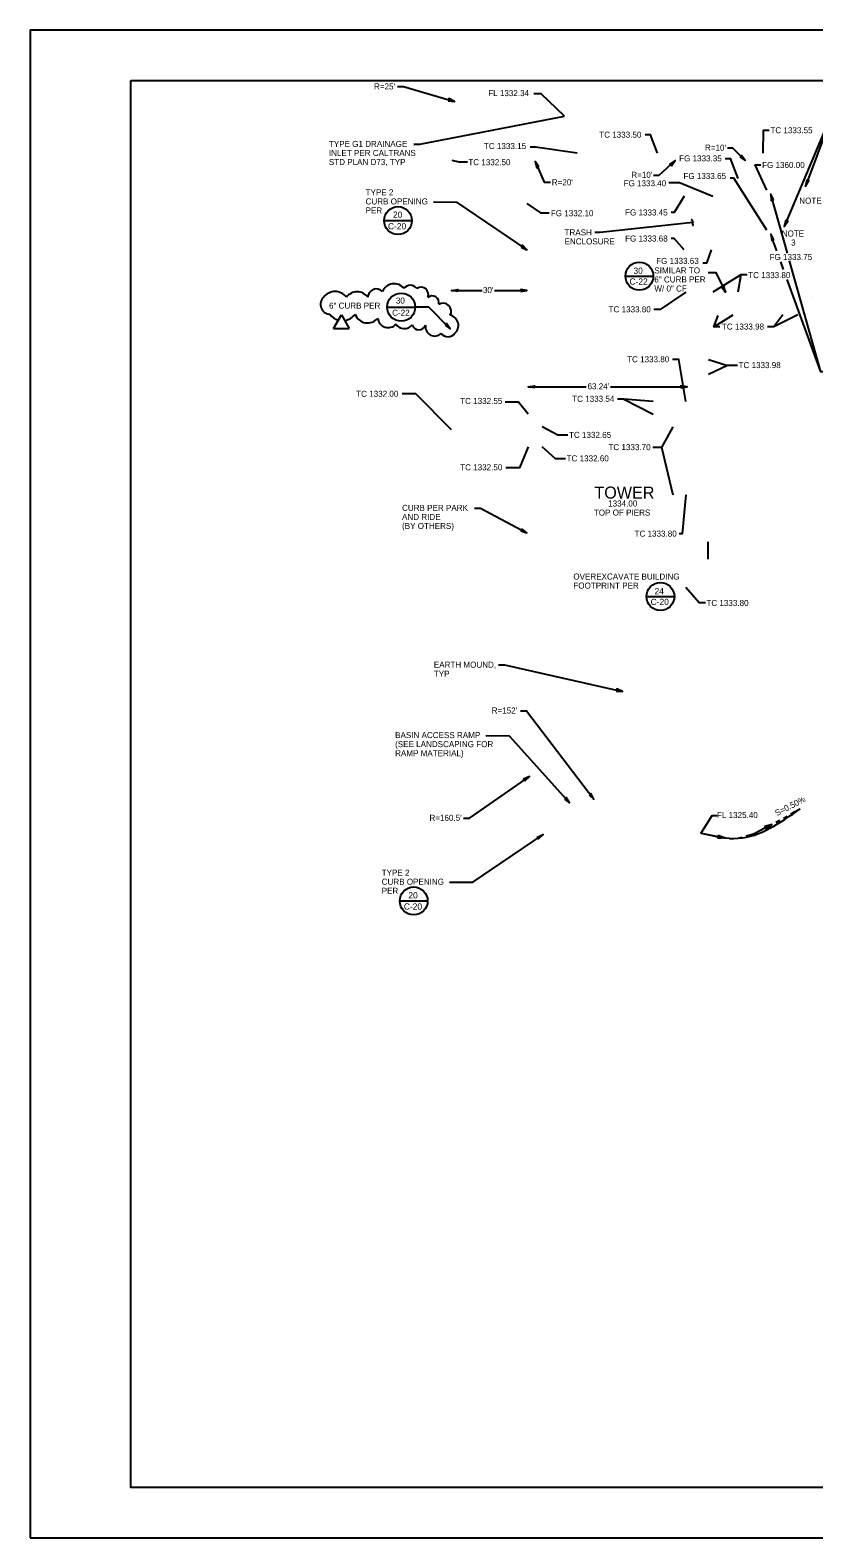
# Model space of a CAD drawing. Extents: x 0 to 3.5, y 0 to 3.39.
# Drawn here: x 0 to 1.299, y 0 to 2.5 of the extents above; entities that cross this region are included whole.
import ezdxf

# ---------------------------------------------------------------- set-up
doc = ezdxf.new("R2010")
doc.units = 0
for name, color, linetype in [('A-FLOR-PATT', 7, 'Continuous'), ('C-FLOW-Swale', 7, 'Continuous'), ('C-MARK', 7, 'Continuous'), ('C-MATC', 7, 'Continuous'), ('C-REVC', 7, 'Continuous'), ('C-TEXT', 7, 'Continuous'), ('C-TEXT-TITL', 7, 'Continuous'), ('G-TTLB-OTLN', 7, 'Continuous'), ('G-TTLB-VIEW', 7, 'Continuous')]:
    doc.layers.add(name, color=color, linetype=linetype)

msp = doc.modelspace()

# ---------------------------------------------------------------- linework, layer by layer
at = {"layer": 'A-FLOR-PATT'}
msp.add_line((1.2971, 2.0571), (1.2969, 2.0571), dxfattribs=at)
at = {"layer": 'C-FLOW-Swale'}
for p, q in [((1.2179, 1.1799), (1.2301, 1.1833)), ((1.2192, 1.1776), (1.2179, 1.1799)), ((1.2192, 1.1776), (1.2204, 1.1752)), ((1.2301, 1.1833), (1.2204, 1.1752)), ((1.14, 1.1628), (1.1395, 1.1602)), ((1.1522, 1.1608), (1.1396, 1.16)), ((1.14, 1.1628), (1.1406, 1.1654)), ((1.1404, 1.1653), (1.1522, 1.1608))]:
    msp.add_line(p, q, dxfattribs=at)
for points in [[(1.2611, 1.2002), (1.2672, 1.2036)], [(1.2672, 1.2036), (1.2765, 1.2088)], [(1.1936, 1.1658), (1.2003, 1.1677), (1.2192, 1.1776)], [(1.2182, 1.1793), (1.221, 1.1807)], [(1.2185, 1.1787), (1.224, 1.1816)], [(1.2189, 1.1781), (1.2271, 1.1824)], [(1.2192, 1.1776), (1.2301, 1.1833)], [(1.2195, 1.177), (1.2277, 1.1813)], [(1.2198, 1.1764), (1.2252, 1.1792)], [(1.2201, 1.1758), (1.2228, 1.1772)], [(1.2364, 1.1865), (1.2385, 1.1877), (1.2426, 1.1899)], [(1.2487, 1.1933), (1.2549, 1.1968)], [(1.1124, 1.1686), (1.14, 1.1628)], [(1.1396, 1.1609), (1.1426, 1.1603)], [(1.1398, 1.1615), (1.1433, 1.1608), (1.1459, 1.1604)], [(1.1399, 1.1622), (1.1434, 1.1615), (1.149, 1.1606)], [(1.14, 1.1628), (1.1435, 1.1621), (1.1522, 1.1608)], [(1.1402, 1.1635), (1.1436, 1.1628), (1.1493, 1.1619)], [(1.1403, 1.1641), (1.1438, 1.1634), (1.1463, 1.163)], [(1.1404, 1.1648), (1.1435, 1.1642)], [(1.1592, 1.1597), (1.1662, 1.1599)], [(1.1733, 1.16), (1.174, 1.16), (1.1801, 1.1618)], [(1.1869, 1.1638), (1.1936, 1.1658)]]:
    msp.add_lwpolyline(points, dxfattribs=at)
msp.add_spline([(1.1124, 1.1686), (1.174, 1.16), (1.2765, 1.2088)], degree=3, dxfattribs=at)
at = {"layer": 'C-MARK'}
for p, q in [((1.3416, 2.3923), (1.2855, 2.2414)), ((1.1784, 2.0941), (1.1315, 2.0653)), ((0.6986, 2.0682), (0.7494, 2.0682)), ((0.7697, 2.0682), (0.8236, 2.0682)), ((1.2475, 2.0277), (1.2331, 2.0083)), ((1.1245, 1.954), (1.1559, 1.9441)), ((0.8257, 1.9086), (0.9219, 1.9086)), ((0.9622, 1.9086), (1.0892, 1.9086)), ((0.9841, 1.8882), (1.0328, 1.8632)), ((1.0474, 1.8081), (1.0661, 1.8424)), ((1.1232, 1.6514), (1.1232, 1.6227))]:
    msp.add_line(p, q, dxfattribs=at)
for points in [[(0.6089, 2.4068), (0.6189, 2.4068), (0.7035, 2.3817)], [(0.8858, 2.3575), (0.8474, 2.3944), (0.835, 2.3944)], [(1.3541, 2.3924), (1.3416, 2.3923), (1.2499, 2.1747)], [(0.6359, 2.3111), (0.6459, 2.3111), (0.8858, 2.3575)], [(1.0399, 2.2958), (1.0282, 2.3265), (1.0194, 2.3265)], [(1.2149, 2.2958), (1.2155, 2.3341), (1.2249, 2.3341)], [(0.9069, 2.2958), (0.8377, 2.306), (0.8289, 2.306)], [(1.1854, 2.2836), (1.1647, 2.3042), (1.1559, 2.3042)], [(0.6992, 2.2843), (0.7109, 2.2819), (0.725, 2.2819)], [(0.8373, 2.2822), (0.8523, 2.2477), (0.8628, 2.2477)], [(1.0694, 2.2836), (1.0424, 2.2589), (1.0336, 2.2589)], [(1.1522, 2.2871), (1.1607, 2.2871), (1.1732, 2.2542)], [(1.2211, 2.2348), (1.2018, 2.2765), (1.2112, 2.2765)], [(1.2211, 2.1681), (1.1668, 2.2547), (1.1606, 2.2547)], [(1.0588, 2.2476), (1.0763, 2.2475), (1.1315, 2.2249)], [(1.2554, 2.13), (1.2277, 2.2282)], [(0.6686, 2.2151), (0.7069, 2.2149), (0.8236, 2.136)], [(0.8236, 2.2125), (0.8463, 2.1971), (0.8604, 2.1971)], [(1.0843, 2.2249), (1.0674, 2.1979), (1.0624, 2.1979)], [(1.0985, 2.1812), (0.9448, 2.1647), (0.936, 2.1647)], [(1.0843, 2.136), (1.0675, 2.1547), (1.0625, 2.1547)], [(1.2376, 2.1341), (1.2312, 2.1517)], [(1.1288, 2.136), (1.1215, 2.1139), (1.1153, 2.1139)], [(1.249, 2.1029), (1.2443, 2.1157)], [(1.3209, 1.9332), (1.3109, 1.9332), (1.2589, 2.1176)], [(1.124, 2.0981), (1.1366, 2.0981), (1.1528, 2.0653)], [(1.1884, 2.0941), (1.1784, 2.0941), (1.1732, 2.0653)], [(1.3209, 1.9332), (1.3109, 1.9332), (1.255, 2.0863)], [(1.0869, 2.0653), (1.0446, 2.0367), (1.034, 2.0367)], [(0.6965, 2.005), (0.6608, 2.0407), (0.6382, 2.0407)], [(1.1436, 2.0083), (1.1336, 2.0083), (1.1657, 2.0278)], [(1.1436, 2.0083), (1.1336, 2.0083), (1.1407, 2.0268)], [(1.2725, 2.0277), (1.2331, 2.0083), (1.2226, 2.0083)], [(1.0869, 1.884), (1.0751, 1.9538), (1.0646, 1.9538)], [(1.1727, 1.9441), (1.1559, 1.9441), (1.1245, 1.929)], [(0.6986, 1.8371), (0.6393, 1.897), (0.6167, 1.897)], [(0.8257, 1.8632), (0.8097, 1.8831), (0.7872, 1.8831)], [(1.0328, 1.884), (0.9841, 1.8882), (0.9736, 1.8882)], [(0.8916, 1.8284), (0.8748, 1.8284), (0.8486, 1.8424)], [(0.8257, 1.809), (0.8111, 1.7745), (0.7885, 1.7745)], [(0.8877, 1.7894), (0.8709, 1.7894), (0.8486, 1.809)], [(1.0661, 1.7292), (1.0474, 1.8081), (1.0324, 1.8081)], [(1.0871, 1.7293), (1.081, 1.6648), (1.0758, 1.6648)], [(0.7367, 1.7072), (0.7467, 1.7072), (0.8236, 1.6662)], [(1.1193, 1.5503), (1.1093, 1.5503), (1.0869, 1.5759)], [(0.7764, 1.4474), (0.7864, 1.4474), (0.9822, 1.4036)], [(0.813, 1.3715), (0.823, 1.3715), (0.9342, 1.2249)], [(0.7556, 1.3302), (0.794, 1.3301), (0.8942, 1.2185)], [(0.7186, 1.1935), (0.7286, 1.1935), (0.8276, 1.2627)], [(1.112, 1.168), (1.1308, 1.198), (1.1388, 1.198)], [(0.6954, 1.0872), (0.7337, 1.0873), (0.8504, 1.1663)]]:
    msp.add_lwpolyline(points, dxfattribs=at)
at = {"layer": 'C-MATC'}
msp.add_line((0.6372, 2.4167), (2.713, 2.4167), dxfattribs=at)
at = {"layer": 'C-REVC'}
for centre, radius, start, end in [((0.6033, 2.0586), 0.0209, 38.7959, 157.6967), ((0.6304, 2.0635), 0.0135, 36.8699, 143.1301), ((0.4977, 2.0452), 0.0164, 133.0869, 266.8793), ((0.5054, 2.0431), 0.0235, 36.8699, 143.1301), ((0.542, 2.0439), 0.0222, 36.8699, 143.1301), ((0.5738, 2.0568), 0.0141, 43.5495, 178.362), ((0.648, 2.0615), 0.0122, 336.9362, 123.7755), ((0.6664, 2.0481), 0.0112, 345.9426, 129.7528), ((0.5177, 2.0445), 0.0261, 216.8699, 254.2871), ((0.5177, 2.0445), 0.0261, 278.7241, 323.1301), ((0.5592, 2.0365), 0.022, 200.435, 320.895), ((0.6842, 2.0335), 0.0137, 332.8796, 120.3027), ((0.6928, 2.0104), 0.0172, 310.8028, 78.1976), ((0.5937, 2.0242), 0.0175, 185.0637, 317.4847), ((0.6204, 2.0218), 0.0167, 214.4063, 320.6665), ((0.6446, 2.0149), 0.0118, 197.978, 338.8776), ((0.6705, 2.0079), 0.0151, 169.7127, 316.0339), ((0.6927, 2.0059), 0.0142, 216.8699, 323.1301)]:
    msp.add_arc(centre, radius, start, end, dxfattribs=at)
at = {"layer": 'C-TEXT'}
for p, q in [((0.5865, 2.1842), (0.6328, 2.1842)), ((0.9867, 2.0921), (1.033, 2.0921)), ((0.5029, 2.0051), (0.516, 2.0277)), ((0.516, 2.0277), (0.529, 2.0051)), ((0.5919, 2.0407), (0.6382, 2.0407)), ((0.5029, 2.0051), (0.529, 2.0051)), ((0.5029, 2.0051), (0.5029, 2.0051)), ((0.529, 2.0051), (0.529, 2.0051)), ((1.0216, 1.5608), (1.0679, 1.5608)), ((0.6126, 1.056), (0.6589, 1.056))]:
    msp.add_line(p, q, dxfattribs=at)
for points in [[(0.693, 2.3829), (0.7035, 2.3817), (0.6941, 2.3864)], [(0.8431, 2.2734), (0.8373, 2.2822), (0.8398, 2.2719)], [(1.063, 2.2752), (1.0694, 2.2836), (1.0605, 2.2779)], [(1.1767, 2.2897), (1.1854, 2.2836), (1.1793, 2.2923)], [(1.2875, 2.2518), (1.2855, 2.2414), (1.2909, 2.2505)], [(1.2323, 2.2187), (1.2277, 2.2282), (1.2287, 2.2177)], [(1.2528, 2.1849), (1.2499, 2.1747), (1.2561, 2.1832)], [(1.2329, 2.1523), (1.2277, 2.1615), (1.2295, 2.1511)], [(0.814, 2.1403), (0.8236, 2.136), (0.816, 2.1434)], [(1.1466, 2.0739), (1.1528, 2.0653), (1.1498, 2.0755)], [(0.709, 2.0664), (0.6986, 2.0682), (0.709, 2.07)], [(0.8132, 2.0664), (0.8236, 2.0682), (0.8132, 2.07)], [(0.6878, 2.011), (0.6965, 2.005), (0.6904, 2.0136)], [(0.8361, 1.9067), (0.8257, 1.9086), (0.8361, 1.9104)], [(1.0788, 1.9067), (1.0892, 1.9086), (1.0788, 1.9104)], [(0.8136, 1.6696), (0.8236, 1.6662), (0.8154, 1.6728)], [(0.9717, 1.4041), (0.9822, 1.4036), (0.9725, 1.4076)], [(0.8202, 1.2552), (0.8276, 1.2627), (0.8181, 1.2582)], [(0.8859, 1.2251), (0.8942, 1.2185), (0.8886, 1.2275)], [(0.9265, 1.2321), (0.9342, 1.2249), (0.9294, 1.2343)], [(0.8407, 1.1619), (0.8504, 1.1663), (0.8428, 1.1589)]]:
    msp.add_lwpolyline(points, close=True, dxfattribs=at)
msp.add_circle((0.6151, 2.0407), 0.0232, dxfattribs=at)
for centre, start, end in [((1.0954, 2.1825), 338.8696, 87.1943), ((1.1011, 2.179), 138.2599, 246.5846)]:
    msp.add_arc(centre, 0.00338, start, end, dxfattribs=at)
for centre in [(0.6098, 2.1842), (1.01, 2.0921), (1.0449, 1.5609), (0.6359, 1.0561)]:
    msp.add_ellipse(centre, major_axis=(0, 0.0232), ratio=0.994695, dxfattribs=at)
at = {"layer": 'G-TTLB-OTLN'}
msp.add_lwpolyline([(0, 0), (3.5, 0), (3.5, 2.5), (0, 2.5)], close=True, dxfattribs=at)
at = {"layer": 'G-TTLB-VIEW'}
msp.add_lwpolyline([(0.1667, 2.4167), (3.0729, 2.4167), (3.0729, 0.0833), (0.1667, 0.0833)], close=True, dxfattribs=at)

# ---------------------------------------------------------------- texts
at = {"layer": 'C-TEXT'}
for s, p in [("R=25'", (0.57, 2.4017)), ('FL 1332.34', (0.7594, 2.3906)), ('TC 1333.50', (0.9434, 2.3217)), ('TC 1333.55', (1.2272, 2.329)), ('TYPE G1 DRAINAGE', (0.4952, 2.3064)), ('INLET PER CALTRANS', (0.4952, 2.2914)), ('TC 1333.15', (0.7523, 2.3028)), ("R=10'", (1.1187, 2.3002)), ('STD PLAN D73, TYP', (0.4952, 2.2764)), ('TC 1332.50', (0.7264, 2.2761)), ('FG 1333.35', (1.0759, 2.2824)), ('FG 1360.00', (1.2134, 2.2715)), ("R=20'", (0.8648, 2.2427)), ('FG 1333.40', (0.9838, 2.2412)), ("R=10'", (0.9966, 2.2551)), ('FG 1333.65', (1.083, 2.2532)), ('TYPE 2', (0.5561, 2.226)), ('CURB OPENING', (0.5561, 2.211)), ('PER', (0.5561, 2.196)), ('FG 1332.10', (0.8632, 2.1915)), ('FG 1333.45', (0.9862, 2.1927)), ('NOTE 3', (1.275, 2.2121)), ('TRASH', (0.8859, 2.1597)), ('ENCLOSURE', (0.8859, 2.1447)), ('FG 1333.68', (0.9863, 2.1495)), ('NOTE', (1.2459, 2.1578)), ('3', (1.2615, 2.1428)), ('FG 1333.75', (1.2258, 2.1189)), ('FG 1333.63', (1.0378, 2.1124)), ('TC 1333.80', (1.1904, 2.0888)), ('30', (0.6063, 2.0466)), ("30'", (0.7506, 2.064)), ('6" CURB PER', (0.4955, 2.0382)), ('C-22', (0.6002, 2.0265)), ('TC 1333.80', (0.959, 2.0321)), ('TC 1333.98', (1.1468, 2.0035)), ('TC 1333.80', (0.9896, 1.9493)), ('TC 1333.98', (1.1744, 1.9396)), ('TC 1332.00', (0.5405, 1.892)), ("63.24'", (0.924, 1.9044)), ('TC 1332.55', (0.7129, 1.8802)), ('TC 1333.54', (0.8986, 1.8837)), ('TC 1332.65', (0.8933, 1.8239)), ('TC 1333.70', (0.9587, 1.8036)), ('TC 1332.50', (0.7129, 1.7702)), ('TC 1332.60', (0.8894, 1.7849)), ('CURB PER PARK', (0.6165, 1.7029)), ('TOP OF PIERS', (0.9345, 1.6951)), ('1334.00', (0.9582, 1.7101)), ('AND RIDE', (0.6165, 1.6879)), ('(BY OTHERS)', (0.6165, 1.6729)), ('TC 1333.80', (1.002, 1.6602)), ('OVEREXCAVATE BUILDING ', (0.9005, 1.589)), ('FOOTPRINT PER', (0.9005, 1.574)), ('TC 1333.80', (1.1211, 1.5452)), ('EARTH MOUND,', (0.6692, 1.4428)), ('TYP', (0.6692, 1.4278)), ("R=152'", (0.7651, 1.3669)), ('BASIN ACCESS RAMP', (0.605, 1.3261)), ('(SEE LANDSCAPING FOR', (0.605, 1.3111)), ('RAMP MATERIAL)', (0.605, 1.2961)), ('FL 1325.40', (1.1386, 1.1935)), ("R=160.5'", (0.6619, 1.1889)), ('TYPE 2', (0.5828, 1.0979)), ('CURB OPENING', (0.5828, 1.0829)), ('PER', (0.5828, 1.0679))]:
    msp.add_text(s, height=0.01, dxfattribs=at).set_placement(p)
for s, height, rotation, p in [('C-20', 0.01042, 360, (0.5932, 2.1696)), ('20', 0.01042, 360, (0.6015, 2.1888)), ('30', 0.01042, 360, (1.0002, 2.0959)), ('SIMILAR TO ', 0.01, 360, (1.0348, 2.0966)), ('C-22', 0.01042, 360, (0.9936, 2.078)), ('W/ 0" CF', 0.01, 360, (1.0348, 2.0666)), ('6" CURB PER', 0.01, 360, (1.0348, 2.0816)), ('24', 0.01042, 360, (1.0351, 1.5646)), ('C-20', 0.01042, 360, (1.0286, 1.5467)), ('S=0.50%', 0.01, 27.2188, (1.2379, 1.1965)), ('C-20', 0.01042, 360, (0.6195, 1.0416)), ('20', 0.01042, 360, (0.627, 1.0603))]:
    msp.add_text(s, height=height, rotation=rotation, dxfattribs=at).set_placement(p)
at = {"layer": 'C-TEXT-TITL'}
msp.add_text('TOWER', height=0.02, dxfattribs=at).set_placement((0.9354, 1.7232))

doc.saveas('drawing.dxf')
